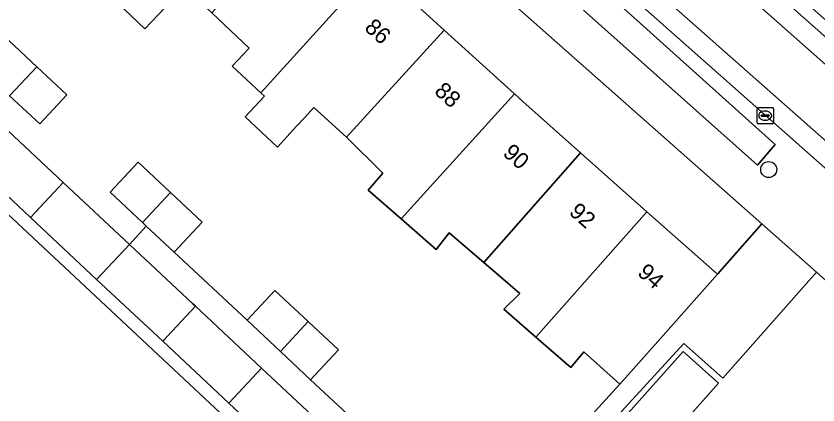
# Model space of a CAD drawing. Extents: x 162073 to 163043, y 381818 to 382561.
# Drawn here: x 162575.66 to 162624.75, y 382181.41 to 382205.18 of the extents above; entities that cross this region are included whole.
import ezdxf

# ---------------------------------------------------------------- set-up
doc = ezdxf.new("R2010")
doc.units = 0
for name, color, linetype in [('IMGEO_Boom', 7, 'Continuous'), ('IMGEO_Erf', 7, 'Continuous'), ('IMGEO_Fietspad_gesloten', 7, 'Continuous'), ('IMGEO_Kolk', 7, 'Continuous'), ('IMGEO_Pand', 7, 'Continuous'), ('IMGEO_Pand_nummerreeks', 7, 'Continuous'), ('IMGEO_Parkeervlak_open', 7, 'Continuous'), ('IMGEO_Rijbaan_lokaal_open', 7, 'Continuous'), ('IMGEO_Voetpad_open', 7, 'Continuous')]:
    doc.layers.add(name, color=color, linetype=linetype)

msp = doc.modelspace()

# ---------------------------------------------------------------- linework, layer by layer
at = {"layer": 'IMGEO_Boom'}
msp.add_circle((162621.73, 382195.8), 0.489, dxfattribs=at)
at = {"layer": 'IMGEO_Erf'}
for points in [[(162592.043, 382218.91), (162584.822, 382225.942), (162573.298, 382238.041), (162570.341, 382235.295), (162574.035, 382231.214), (162577.783, 382227.419), (162581.647, 382223.506), (162585.757, 382219.345), (162586.991, 382218.096), (162589.637, 382215.563), (162592.295, 382213.017), (162593.539, 382211.887), (162597.618, 382208.184), (162601.869, 382204.326), (162606.169, 382200.422), (162606.685, 382199.954), (162610.219, 382196.821), (162614.278, 382193.221), (162618.589, 382189.398), (162621.309, 382192.475), (162605.774, 382206.205)], [(162548.041, 382218.424), (162538.119, 382206.437), (162539.554, 382205.251), (162540.532, 382204.442), (162542.367, 382202.925), (162543.981, 382201.47), (162544.28, 382201.223), (162546.555, 382199.341), (162550.802, 382195.829), (162555.049, 382192.317), (162559.295, 382188.805), (162563.542, 382185.293), (162567.789, 382181.781), (162572.036, 382178.268), (162576.283, 382174.756), (162580.53, 382171.244), (162584.777, 382167.732), (162589.023, 382164.22), (162593.393, 382160.606), (162600.588, 382169.306)], [(162614.479, 382178.031), (162612.298, 382179.971), (162616.486, 382184.681), (162618.667, 382182.74)]]:
    msp.add_lwpolyline(points, close=True, dxfattribs=at)
for points in [[(162585.97, 382206.962), (162583.552, 382204.406), (162581.46, 382206.395)], [(162604.078, 382173.321), (162612.622, 382182.688), (162610.409, 382184.652), (162609.622, 382183.691), (162607.479, 382185.553), (162605.516, 382187.259), (162606.503, 382188.221), (162604.283, 382190.125), (162602.167, 382191.94), (162601.381, 382190.918), (162599.238, 382192.785), (162597.215, 382194.548), (162598.112, 382195.578), (162595.882, 382197.782), (162593.887, 382199.584), (162593.315, 382198.964), (162592.832, 382198.441), (162591.663, 382197.174), (162589.689, 382199.02), (162590.866, 382200.279), (162590.638, 382200.492), (162588.892, 382202.125), (162589.936, 382203.209), (162587.637, 382205.384)], [(162574.867, 382204.006), (162576.925, 382202.085), (162578.766, 382200.367), (162577.105, 382198.587), (162575.264, 382200.306)], [(162574.5, 382198.78), (162578.548, 382195.002), (162582.596, 382191.225), (162583.626, 382192.346), (162583.395, 382192.562), (162581.416, 382194.408), (162583.128, 382196.243), (162585.107, 382194.397), (162587.054, 382192.58), (162585.341, 382190.745), (162589.796, 382186.587), (162591.496, 382188.409), (162593.538, 382186.505), (162595.391, 382184.775), (162593.69, 382182.953), (162598.213, 382178.739)], [(162638.741, 382177.42), (162626.716, 382187.697), (162624.656, 382189.517), (162618.931, 382183.038), (162616.534, 382185.157), (162605.947, 382173.633)]]:
    msp.add_lwpolyline(points, dxfattribs=at)
at = {"layer": 'IMGEO_Fietspad_gesloten'}
for points in [[(162601.77, 382216.788), (162606.944, 382212.014), (162640.048, 382182.752), (162640.86, 382183.603), (162628.624, 382194.55), (162608.204, 382212.566), (162602.641, 382217.615)], [(162610.213, 382215.487), (162643.217, 382186.312), (162644.019, 382187.212), (162624.584, 382204.454), (162610.981, 382216.511)]]:
    msp.add_lwpolyline(points, dxfattribs=at)
at = {"layer": 'IMGEO_Kolk'}
for p, q in [((162621.017, 382198.668), (162621.017, 382199.52)), ((162621.092, 382199.594), (162621.944, 382199.594)), ((162621.505, 382199.374), (162621.53, 382199.374)), ((162622.018, 382199.52), (162622.018, 382198.668)), ((162621.276, 382199.088), (162621.276, 382199.1)), ((162621.714, 382199.051), (162621.316, 382199.051)), ((162621.319, 382199.137), (162621.717, 382199.137)), ((162621.528, 382198.814), (162621.503, 382198.814)), ((162621.76, 382199.1), (162621.76, 382199.088)), ((162621.944, 382198.594), (162621.092, 382198.594))]:
    msp.add_line(p, q, dxfattribs=at)
for points in [[(162621.017, 382198.668), (162621.017, 382199.52)], [(162621.092, 382199.594), (162621.944, 382199.594)], [(162622.018, 382199.52), (162622.018, 382198.668)], [(162621.944, 382198.594), (162621.092, 382198.594)]]:
    msp.add_lwpolyline(points, dxfattribs=at)
for centre, radius, start, end in [((162621.094, 382199.518), 0.0765, 91.552, 178.448), ((162621.094, 382199.518), 0.0765, 91.552, 178.448), ((162621.942, 382199.518), 0.0765, 1.552, 88.448), ((162621.942, 382199.518), 0.0765, 1.552, 88.448), ((162621.316, 382199.097), 0.0403, 85.8775, 175.7526), ((162621.313, 382199.087), 0.0366, 178.938, 274.7102), ((162621.717, 382199.094), 0.043, 264.8664, 352.4533), ((162621.721, 382199.099), 0.0386, 1.7309, 96.639), ((162621.094, 382198.67), 0.0765, 181.552, 268.448), ((162621.094, 382198.67), 0.0765, 181.552, 268.448), ((162621.942, 382198.67), 0.0765, 271.552, 358.448), ((162621.942, 382198.67), 0.0765, 271.552, 358.448)]:
    msp.add_arc(centre, radius, start, end, dxfattribs=at)
for centre, major_axis, ratio, start_param, end_param in [((162621.504, 382199.094), (-0.387, 0.002), 0.722429, 4.712389, 7.853982), ((162621.529, 382199.094), (-0.39, 0.002), 0.717154, 1.570796, 4.712389)]:
    msp.add_ellipse(centre, major_axis=major_axis, ratio=ratio, start_param=start_param, end_param=end_param, dxfattribs=at)
at = {"layer": 'IMGEO_Pand'}
for points in [[(162593.539, 382211.887), (162592.295, 382213.017), (162589.637, 382215.563), (162582.409, 382208.015), (162582.72, 382207.719), (162581.46, 382206.395), (162583.552, 382204.406), (162585.97, 382206.962), (162587.637, 382205.384)], [(162590.638, 382200.492), (162597.618, 382208.184), (162593.539, 382211.887), (162587.637, 382205.384), (162589.936, 382203.209), (162588.892, 382202.125)], [(162601.869, 382204.326), (162597.618, 382208.184), (162590.638, 382200.492), (162590.866, 382200.279), (162589.689, 382199.02), (162591.663, 382197.174), (162592.832, 382198.441), (162593.315, 382198.964), (162593.887, 382199.584), (162595.882, 382197.782)], [(162606.169, 382200.422), (162601.869, 382204.326), (162595.882, 382197.782), (162598.112, 382195.578), (162597.215, 382194.548), (162599.238, 382192.785)], [(162576.925, 382202.085), (162574.867, 382204.006), (162573.206, 382202.226), (162575.264, 382200.306)], [(162576.925, 382202.085), (162575.264, 382200.306), (162577.105, 382198.587), (162578.766, 382200.367)], [(162610.219, 382196.821), (162606.685, 382199.954), (162606.169, 382200.422), (162599.238, 382192.785), (162601.381, 382190.918), (162602.167, 382191.94), (162604.283, 382190.125)], [(162578.548, 382195.002), (162574.5, 382198.78), (162572.505, 382196.648), (162576.548, 382192.865)], [(162610.219, 382196.821), (162604.283, 382190.125), (162606.503, 382188.221), (162605.516, 382187.259), (162607.479, 382185.553), (162614.278, 382193.221)], [(162583.395, 382192.562), (162585.107, 382194.397), (162583.128, 382196.243), (162581.416, 382194.408)], [(162578.548, 382195.002), (162576.548, 382192.865), (162580.591, 382189.082), (162582.596, 382191.225)], [(162585.107, 382194.397), (162583.395, 382192.562), (162583.626, 382192.346), (162585.341, 382190.745), (162587.054, 382192.58)], [(162607.479, 382185.553), (162609.622, 382183.691), (162610.409, 382184.652), (162612.622, 382182.688), (162615.267, 382185.662), (162618.589, 382189.398), (162614.278, 382193.221)], [(162580.591, 382189.082), (162584.634, 382185.299), (162586.644, 382187.447), (162586.481, 382187.6), (162582.596, 382191.225)], [(162589.796, 382186.587), (162591.837, 382184.682), (162593.538, 382186.505), (162591.496, 382188.409)], [(162586.644, 382187.447), (162584.634, 382185.299), (162588.678, 382181.516), (162590.688, 382183.664)], [(162593.538, 382186.505), (162591.837, 382184.682), (162593.69, 382182.953), (162595.391, 382184.775)], [(162614.479, 382178.031), (162618.667, 382182.74), (162616.486, 382184.681), (162612.298, 382179.971)], [(162592.721, 382177.733), (162594.731, 382179.881), (162590.688, 382183.664), (162588.678, 382181.516)]]:
    msp.add_lwpolyline(points, close=True, dxfattribs=at)
at = {"layer": 'IMGEO_Parkeervlak_open'}
msp.add_lwpolyline([(162610.404, 382205.549), (162621.039, 382196.059), (162622.118, 382197.321), (162611.241, 382207.115)], dxfattribs=at)
at = {"layer": 'IMGEO_Rijbaan_lokaal_open'}
msp.add_lwpolyline([(162602.641, 382217.615), (162608.204, 382212.566), (162628.624, 382194.55), (162640.86, 382183.603), (162643.217, 382186.312), (162610.213, 382215.487)], dxfattribs=at)
at = {"layer": 'IMGEO_Voetpad_open'}
for points in [[(162515.515, 382317.726), (162524.856, 382301.801), (162530.981, 382292.245), (162532.058, 382290.664), (162540.59, 382278.138), (162545.965, 382270.851), (162557.981, 382255.464), (162562.574, 382250), (162567.838, 382244.089), (162572.157, 382239.239), (162572.556, 382238.82), (162573.298, 382238.041), (162584.822, 382225.942), (162592.043, 382218.91), (162605.774, 382206.205), (162621.309, 382192.475), (162624.656, 382189.517), (162626.716, 382187.697), (162638.741, 382177.42), (162641.717, 382174.636)], [(162592.721, 382177.733), (162588.678, 382181.516), (162584.634, 382185.299), (162580.591, 382189.082), (162576.548, 382192.865), (162572.505, 382196.648), (162568.462, 382200.431), (162564.419, 382204.214), (162560.376, 382207.997), (162556.332, 382211.78), (162552.289, 382215.563), (162547.706, 382219.852)], [(162548.041, 382218.424), (162600.588, 382169.306)], [(162610.981, 382216.511), (162624.584, 382204.454), (162644.019, 382187.212), (162658.031, 382174.847), (162658.585, 382175.454), (162625.089, 382205.044), (162613.365, 382215.409), (162614.546, 382216.706), (162612.735, 382218.35), (162611.547, 382217.024)], [(162640.817, 382182.048), (162640.048, 382182.752), (162606.944, 382212.014), (162601.77, 382216.788)], [(162611.241, 382207.115), (162622.118, 382197.321), (162621.039, 382196.059)], [(162621.039, 382196.059), (162610.404, 382205.549)], [(162605.947, 382173.633), (162616.534, 382185.157), (162618.931, 382183.038), (162624.656, 382189.517), (162621.309, 382192.475), (162618.589, 382189.398), (162615.267, 382185.662), (162612.622, 382182.688), (162604.078, 382173.321)], [(162598.213, 382178.739), (162593.69, 382182.953), (162591.837, 382184.682), (162589.796, 382186.587), (162585.341, 382190.745), (162583.626, 382192.346), (162582.596, 382191.225), (162586.481, 382187.6), (162586.644, 382187.447), (162590.688, 382183.664), (162594.731, 382179.881)]]:
    msp.add_lwpolyline(points, dxfattribs=at)

# ---------------------------------------------------------------- texts
at = {"layer": 'IMGEO_Pand_nummerreeks'}
for s, rotation, p in [('86', 317.773, (162596.928, 382204.383)), ('88', 317.7774, (162601.206, 382200.499)), ('90', 318.3436, (162605.399, 382196.718)), ('92', 318.4445, (162609.453, 382193.117)), ('94', 318.4193, (162613.639, 382189.405))]:
    msp.add_text(s, height=1, rotation=rotation, dxfattribs=at).set_placement(p)

doc.saveas('drawing.dxf')
